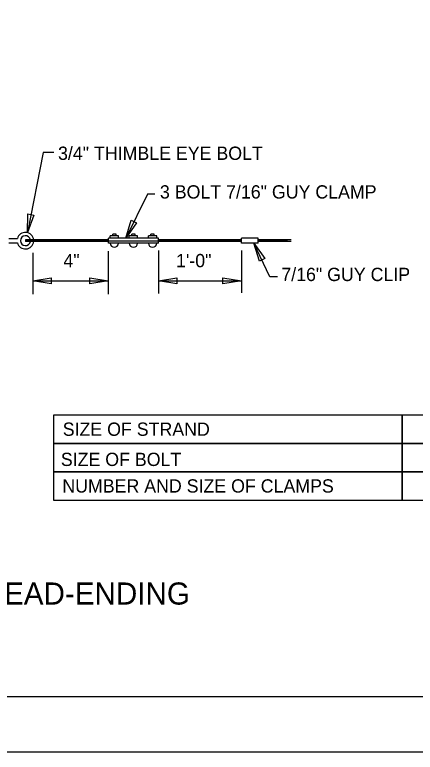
# Model space of a CAD drawing. Extents: x 1299104.8 to 1299141.6, y 239639.8 to 239661.8.
# Drawn here: x 1299110.83 to 1299114.45, y 239639.79 to 239646.46 of the extents above; entities that cross this region are included whole.
import ezdxf

# ---------------------------------------------------------------- set-up
doc = ezdxf.new("R2010")
doc.units = 0
for name, color, linetype in [('DIM TXT', 7, 'Continuous'), ('GS_plotshape_p', 7, 'Continuous'), ('Level 1', 7, 'Continuous')]:
    doc.layers.add(name, color=color, linetype=linetype)

msp = doc.modelspace()

# ---------------------------------------------------------------- linework, layer by layer
at = {"layer": 'DIM TXT'}
for p, q in [((1299111.0926, 239645.2155), (1299110.949, 239644.4905)), ((1299111.1877, 239645.2155), (1299111.0926, 239645.2155)), ((1299112.0334, 239644.8375), (1299111.838, 239644.44)), ((1299112.1002, 239644.8375), (1299112.0334, 239644.8375)), ((1299111.7492, 239644.4775), (1299111.7192, 239644.4775)), ((1299111.7192, 239644.4625), (1299111.7192, 239644.4775)), ((1299111.7492, 239644.4625), (1299111.7492, 239644.4775)), ((1299111.9217, 239644.4775), (1299111.8917, 239644.4775)), ((1299111.8917, 239644.4625), (1299111.8917, 239644.4775)), ((1299111.9217, 239644.4625), (1299111.9217, 239644.4775)), ((1299112.0942, 239644.4775), (1299112.0642, 239644.4775)), ((1299112.0642, 239644.4625), (1299112.0642, 239644.4775)), ((1299112.0942, 239644.4625), (1299112.0942, 239644.4775)), ((1299110.7817, 239644.4362), (1299110.8591, 239644.4362)), ((1299111.6817, 239644.425), (1299110.9317, 239644.425)), ((1299110.9317, 239644.425), (1299110.9467, 239644.41)), ((1299110.9317, 239644.425), (1299110.9317, 239644.41)), ((1299111.6817, 239644.41), (1299110.9317, 239644.41)), ((1299110.9467, 239644.425), (1299110.9617, 239644.41)), ((1299110.9617, 239644.425), (1299110.9767, 239644.41)), ((1299110.9767, 239644.425), (1299110.9917, 239644.41)), ((1299110.9917, 239644.425), (1299111.0067, 239644.41)), ((1299111.0067, 239644.425), (1299111.0217, 239644.41)), ((1299111.0217, 239644.425), (1299111.0367, 239644.41)), ((1299111.0367, 239644.425), (1299111.0517, 239644.41)), ((1299111.0517, 239644.425), (1299111.0667, 239644.41)), ((1299111.0667, 239644.425), (1299111.0817, 239644.41)), ((1299111.0817, 239644.425), (1299111.0967, 239644.41)), ((1299111.0967, 239644.425), (1299111.1117, 239644.41)), ((1299111.1117, 239644.425), (1299111.1267, 239644.41)), ((1299111.1267, 239644.425), (1299111.1417, 239644.41)), ((1299111.1417, 239644.425), (1299111.1567, 239644.41)), ((1299111.1567, 239644.425), (1299111.1717, 239644.41)), ((1299111.1717, 239644.425), (1299111.1867, 239644.41)), ((1299111.1867, 239644.425), (1299111.2017, 239644.41)), ((1299111.2017, 239644.425), (1299111.2167, 239644.41)), ((1299111.2167, 239644.425), (1299111.2317, 239644.41)), ((1299111.2317, 239644.425), (1299111.2467, 239644.41)), ((1299111.2467, 239644.425), (1299111.2617, 239644.41)), ((1299111.2617, 239644.425), (1299111.2767, 239644.41)), ((1299111.2767, 239644.425), (1299111.2917, 239644.41)), ((1299111.2917, 239644.425), (1299111.3067, 239644.41)), ((1299111.3067, 239644.425), (1299111.3217, 239644.41)), ((1299111.3217, 239644.425), (1299111.3367, 239644.41)), ((1299111.3367, 239644.425), (1299111.3517, 239644.41)), ((1299111.3517, 239644.425), (1299111.3667, 239644.41)), ((1299111.3667, 239644.425), (1299111.3817, 239644.41)), ((1299111.3817, 239644.425), (1299111.3967, 239644.41)), ((1299111.3967, 239644.425), (1299111.4117, 239644.41)), ((1299111.4117, 239644.425), (1299111.4267, 239644.41)), ((1299111.4267, 239644.425), (1299111.4417, 239644.41)), ((1299111.4417, 239644.425), (1299111.4567, 239644.41)), ((1299111.4567, 239644.425), (1299111.4717, 239644.41)), ((1299111.4717, 239644.425), (1299111.4867, 239644.41)), ((1299111.4867, 239644.425), (1299111.5017, 239644.41)), ((1299111.5017, 239644.425), (1299111.5167, 239644.41)), ((1299111.5167, 239644.425), (1299111.5317, 239644.41)), ((1299111.5317, 239644.425), (1299111.5467, 239644.41)), ((1299111.5467, 239644.425), (1299111.5617, 239644.41)), ((1299111.5617, 239644.425), (1299111.5767, 239644.41)), ((1299111.5767, 239644.425), (1299111.5917, 239644.41)), ((1299111.5917, 239644.425), (1299111.6067, 239644.41)), ((1299111.6067, 239644.425), (1299111.6217, 239644.41)), ((1299111.6217, 239644.425), (1299111.6367, 239644.41)), ((1299111.6367, 239644.425), (1299111.6517, 239644.41)), ((1299111.6517, 239644.425), (1299111.6667, 239644.41)), ((1299111.6667, 239644.425), (1299111.6817, 239644.41)), ((1299112.1317, 239644.44), (1299111.6817, 239644.44)), ((1299111.6817, 239644.395), (1299111.6817, 239644.44)), ((1299111.6817, 239644.4175), (1299112.1317, 239644.4175)), ((1299111.7717, 239644.4625), (1299111.6967, 239644.4625)), ((1299111.6967, 239644.44), (1299111.6967, 239644.4625)), ((1299111.7717, 239644.44), (1299111.7717, 239644.4625)), ((1299111.9442, 239644.4625), (1299111.8692, 239644.4625)), ((1299111.8692, 239644.44), (1299111.8692, 239644.4625)), ((1299111.9442, 239644.44), (1299111.9442, 239644.4625)), ((1299112.1167, 239644.4625), (1299112.0417, 239644.4625)), ((1299112.0417, 239644.44), (1299112.0417, 239644.4625)), ((1299112.1167, 239644.44), (1299112.1167, 239644.4625)), ((1299112.1317, 239644.395), (1299112.1317, 239644.44)), ((1299112.8817, 239644.425), (1299112.1317, 239644.425)), ((1299112.1317, 239644.425), (1299112.1467, 239644.41)), ((1299112.8817, 239644.41), (1299112.1317, 239644.41)), ((1299112.1467, 239644.425), (1299112.1617, 239644.41)), ((1299112.1617, 239644.425), (1299112.1767, 239644.41)), ((1299112.1767, 239644.425), (1299112.1917, 239644.41)), ((1299112.1917, 239644.425), (1299112.2067, 239644.41)), ((1299112.2067, 239644.425), (1299112.2217, 239644.41)), ((1299112.2217, 239644.425), (1299112.2367, 239644.41)), ((1299112.2367, 239644.425), (1299112.2517, 239644.41)), ((1299112.2517, 239644.425), (1299112.2667, 239644.41)), ((1299112.2667, 239644.425), (1299112.2817, 239644.41)), ((1299112.2817, 239644.425), (1299112.2967, 239644.41)), ((1299112.2967, 239644.425), (1299112.3117, 239644.41)), ((1299112.3117, 239644.425), (1299112.3267, 239644.41)), ((1299112.3267, 239644.425), (1299112.3417, 239644.41)), ((1299112.3417, 239644.425), (1299112.3567, 239644.41)), ((1299112.3567, 239644.425), (1299112.3717, 239644.41)), ((1299112.3717, 239644.425), (1299112.3867, 239644.41)), ((1299112.3867, 239644.425), (1299112.4017, 239644.41)), ((1299112.4017, 239644.425), (1299112.4167, 239644.41)), ((1299112.4167, 239644.425), (1299112.4317, 239644.41)), ((1299112.4317, 239644.425), (1299112.4467, 239644.41)), ((1299112.4467, 239644.425), (1299112.4617, 239644.41)), ((1299112.4617, 239644.425), (1299112.4767, 239644.41)), ((1299112.4767, 239644.425), (1299112.4917, 239644.41)), ((1299112.4917, 239644.425), (1299112.5067, 239644.41)), ((1299112.5067, 239644.425), (1299112.5217, 239644.41)), ((1299112.5217, 239644.425), (1299112.5367, 239644.41)), ((1299112.5367, 239644.425), (1299112.5517, 239644.41)), ((1299112.5517, 239644.425), (1299112.5667, 239644.41)), ((1299112.5667, 239644.425), (1299112.5817, 239644.41)), ((1299112.5817, 239644.425), (1299112.5967, 239644.41)), ((1299112.5967, 239644.425), (1299112.6117, 239644.41)), ((1299112.6117, 239644.425), (1299112.6267, 239644.41)), ((1299112.6267, 239644.425), (1299112.6417, 239644.41)), ((1299112.6417, 239644.425), (1299112.6567, 239644.41)), ((1299112.6567, 239644.425), (1299112.6717, 239644.41)), ((1299112.6717, 239644.425), (1299112.6867, 239644.41)), ((1299112.6867, 239644.425), (1299112.7017, 239644.41)), ((1299112.7017, 239644.425), (1299112.7167, 239644.41)), ((1299112.7167, 239644.425), (1299112.7317, 239644.41)), ((1299112.7317, 239644.425), (1299112.7467, 239644.41)), ((1299112.7467, 239644.425), (1299112.7617, 239644.41)), ((1299112.7617, 239644.425), (1299112.7767, 239644.41)), ((1299112.7767, 239644.425), (1299112.7917, 239644.41)), ((1299112.7917, 239644.425), (1299112.8067, 239644.41)), ((1299112.8067, 239644.425), (1299112.8217, 239644.41)), ((1299112.8217, 239644.425), (1299112.8367, 239644.41)), ((1299112.8367, 239644.425), (1299112.8517, 239644.41)), ((1299112.8517, 239644.425), (1299112.8667, 239644.41)), ((1299112.8667, 239644.425), (1299112.8817, 239644.41)), ((1299113.0317, 239644.44), (1299112.8817, 239644.44)), ((1299112.8817, 239644.395), (1299112.8817, 239644.44)), ((1299113.0317, 239644.395), (1299113.0317, 239644.44)), ((1299113.3317, 239644.425), (1299113.0317, 239644.425)), ((1299113.0317, 239644.425), (1299113.0467, 239644.41)), ((1299113.3317, 239644.41), (1299113.0317, 239644.41)), ((1299113.0467, 239644.425), (1299113.0617, 239644.41)), ((1299113.0617, 239644.425), (1299113.0767, 239644.41)), ((1299113.0767, 239644.425), (1299113.0917, 239644.41)), ((1299113.0917, 239644.425), (1299113.1067, 239644.41)), ((1299113.1067, 239644.425), (1299113.1217, 239644.41)), ((1299113.1217, 239644.425), (1299113.1367, 239644.41)), ((1299113.1367, 239644.425), (1299113.1517, 239644.41)), ((1299113.1517, 239644.425), (1299113.1667, 239644.41)), ((1299113.1667, 239644.425), (1299113.1817, 239644.41)), ((1299113.1817, 239644.425), (1299113.1967, 239644.41)), ((1299113.1967, 239644.425), (1299113.2117, 239644.41)), ((1299113.2117, 239644.425), (1299113.2267, 239644.41)), ((1299113.2267, 239644.425), (1299113.2417, 239644.41)), ((1299113.2417, 239644.425), (1299113.2567, 239644.41)), ((1299113.2567, 239644.425), (1299113.2717, 239644.41)), ((1299113.2717, 239644.425), (1299113.2867, 239644.41)), ((1299113.2867, 239644.425), (1299113.3017, 239644.41)), ((1299110.7817, 239644.3987), (1299110.8591, 239644.3987)), ((1299112.1317, 239644.395), (1299111.6817, 239644.395)), ((1299113.0317, 239644.395), (1299112.8817, 239644.395)), ((1299113.1386, 239644.0911), (1299112.9947, 239644.395)), ((1299110.9969, 239644.3068), (1299110.9969, 239643.9333)), ((1299111.6785, 239644.3217), (1299111.6785, 239643.9333)), ((1299112.1317, 239644.3282), (1299112.1317, 239643.9399)), ((1299112.8817, 239644.3282), (1299112.8817, 239643.9448)), ((1299113.208, 239644.0911), (1299113.1386, 239644.0911)), ((1299110.9969, 239644.0551), (1299111.6785, 239644.0551)), ((1299112.1317, 239644.0551), (1299112.8817, 239644.0551))]:
    msp.add_line(p, q, dxfattribs=at)
for points in [[(1299110.9524, 239644.6595), (1299111.0059, 239644.6497), (1299110.949, 239644.4905)], [(1299111.8852, 239644.6023), (1299111.9343, 239644.5789), (1299111.838, 239644.44)], [(1299113.0925, 239644.2571), (1299113.0437, 239644.2332), (1299112.9947, 239644.395)], [(1299111.1637, 239644.0823), (1299111.1637, 239644.0279), (1299110.9969, 239644.0551)], [(1299111.5117, 239644.0279), (1299111.5117, 239644.0823), (1299111.6785, 239644.0551)], [(1299112.2986, 239644.0823), (1299112.2986, 239644.0279), (1299112.1317, 239644.0551)], [(1299112.7149, 239644.0279), (1299112.7149, 239644.0823), (1299112.8817, 239644.0551)], [(1299111.1868, 239642.8425), (1299114.3332, 239642.8425), (1299114.3332, 239642.5847), (1299111.1868, 239642.5847)], [(1299114.3332, 239642.8425), (1299116.4693, 239642.8425), (1299116.4693, 239642.5847), (1299114.3332, 239642.5847)], [(1299111.1868, 239642.5847), (1299114.3332, 239642.5847), (1299114.3332, 239642.327), (1299111.1868, 239642.327)], [(1299114.3332, 239642.5847), (1299116.4693, 239642.5847), (1299116.4693, 239642.327), (1299114.3332, 239642.327)], [(1299111.1868, 239642.327), (1299114.3332, 239642.327), (1299114.3332, 239642.0693), (1299111.1868, 239642.0693)], [(1299114.3332, 239642.327), (1299116.4693, 239642.327), (1299116.4693, 239642.0693), (1299114.3332, 239642.0693)]]:
    msp.add_lwpolyline(points, close=True, dxfattribs=at)
for centre, radius, start, end in [((1299110.9317, 239644.4175), 0.075, 5.73917, 165.52249), ((1299110.9317, 239644.4175), 0.075, 194.47751, 354.26083), ((1299110.9317, 239644.4175), 0.045, 9.59407, 350.40593), ((1299111.7342, 239644.395), 0.0375, 180, 0), ((1299111.9067, 239644.395), 0.0375, 180, 0), ((1299112.0792, 239644.395), 0.0375, 180, 0)]:
    msp.add_arc(centre, radius, start, end, dxfattribs=at)
at = {"layer": 'GS_plotshape_p'}
msp.add_lwpolyline([(1299104.8019, 239661.7913), (1299138.8019, 239661.7913), (1299138.8019, 239639.7913), (1299104.8019, 239639.7913)], close=True, dxfattribs=at)
at = {"layer": 'Level 1'}
msp.add_lwpolyline([(1299138.3019, 239640.2913), (1299106.3019, 239640.2913), (1299106.3019, 239661.2913), (1299138.3019, 239661.2913)], close=True, dxfattribs=at)

# ---------------------------------------------------------------- texts
at = {"layer": 'DIM TXT'}
for s, height, p in [('3/4" THIMBLE EYE BOLT', 0.12, (1299111.2256, 239645.1482)), ('3 BOLT 7/16" GUY CLAMP', 0.12, (1299112.1458, 239644.7987)), ('4"', 0.12, (1299111.2745, 239644.1775)), ('1\'-0"', 0.12, (1299112.2915, 239644.1775)), ('7/16" GUY CLIP', 0.12, (1299113.2424, 239644.0522)), ('SIZE OF STRAND', 0.12, (1299111.2681, 239642.6528)), ('SIZE OF BOLT', 0.12, (1299111.2509, 239642.3799)), ('NUMBER AND SIZE OF CLAMPS', 0.12, (1299111.2642, 239642.1395)), ('SUSPENSION STRAND DEAD-ENDING', 0.2, (1299107.5427, 239641.1267))]:
    msp.add_text(s, height=height, dxfattribs=at).set_placement(p)

doc.saveas('drawing.dxf')
